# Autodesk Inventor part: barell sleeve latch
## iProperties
Created: 2006-04
Part Number: barell sleeve latch
Document SubType Name: Modeling
Designer: Калинин
Author: Калинин
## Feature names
1. Выдавливание1 [Extrusion]
2. Сдвиг1
3. Сопряжение1 [Fillet]
4. Сопряжение2 [Fillet]
